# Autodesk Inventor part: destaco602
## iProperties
Title: destaco602
Author: GJOHNST2
Shininess: 20.0
Length Units: 11272
Angle Units: 11286
Time Units: 11279
Mass Units: 11290
Length Display Precision: 3
Angle Display Precision: 2
Compacted: True
PropertySet Name: _Private Model Information
Created: 2001-11
Part Number: body
Document SubType Name: Modeling
Designer: GJOHNST2
Control State: 0
Master: False
Checked Out: False
PropertySet Name: Design Tracking Control
Density: 0.0
Volumn: 0.0
Area: 0.0
PropertySet Name: Model Information
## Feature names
1. Extrusion1
2. Extrusion2
3. Chamfer1
4. Hole1
5. Hole2
